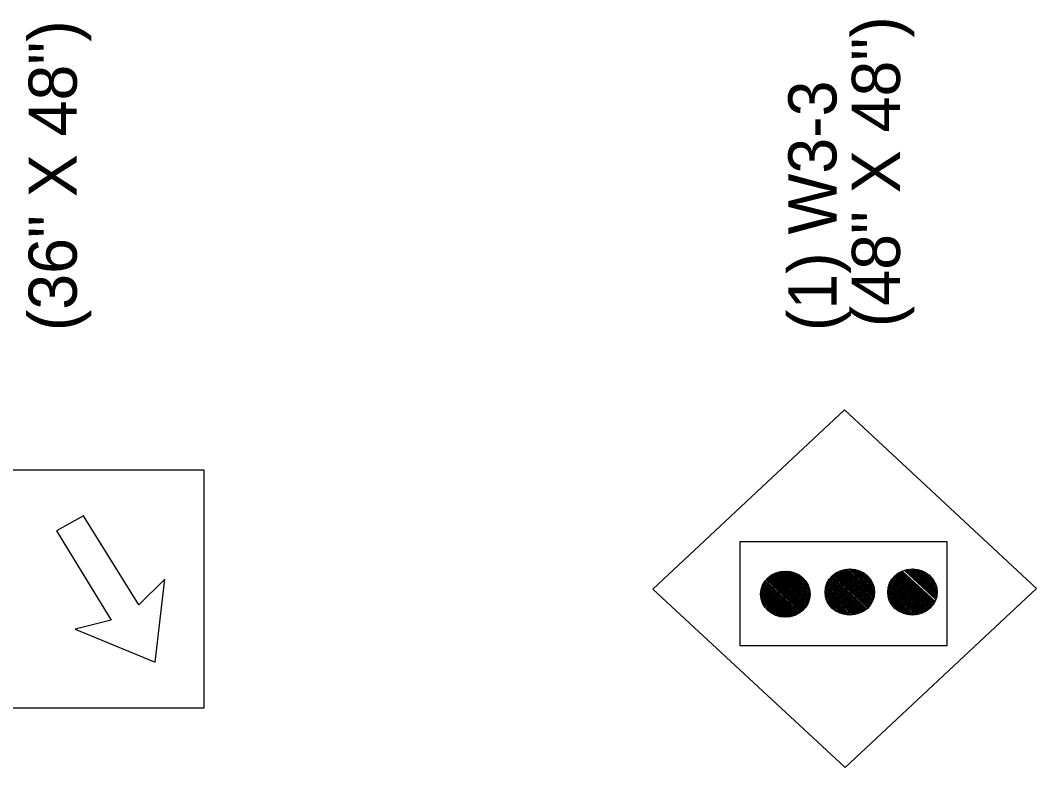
# Model space of a CAD drawing. Extents: x 1807779 to 1818251, y 673292 to 678849.
# Drawn here: x 1811509.5 to 1811641.6, y 676750 to 676847.2 of the extents above; entities that cross this region are included whole.
import ezdxf

# ---------------------------------------------------------------- set-up
doc = ezdxf.new("R2010")
doc.units = 0
doc.layers.add('Default', color=7, linetype='Continuous')

msp = doc.modelspace()

# ---------------------------------------------------------------- linework, layer by layer
at = {"layer": 'Default'}
for p, q in [((1811616.61, 676796.54), (1811591.73, 676773.26)), ((1811616.61, 676796.54), (1811641.6, 676773.34)), ((1811612, 676771.68), (1811607.95, 676775.45)), ((1811612.05, 676771.82), (1811608.11, 676775.5)), ((1811612.09, 676771.97), (1811608.27, 676775.53)), ((1811612.12, 676772.13), (1811608.43, 676775.56)), ((1811612.14, 676772.29), (1811608.61, 676775.58)), ((1811612.16, 676772.46), (1811608.79, 676775.6)), ((1811612.16, 676772.64), (1811608.99, 676775.6)), ((1811612.15, 676772.84), (1811609.2, 676775.59)), ((1811612.12, 676773.05), (1811609.42, 676775.57)), ((1811612.08, 676773.27), (1811609.66, 676775.52)), ((1811612, 676773.53), (1811609.94, 676775.45)), ((1811620.08, 676771.32), (1811615.66, 676775.44)), ((1811620.15, 676771.44), (1811615.78, 676775.51)), ((1811620.22, 676771.56), (1811615.91, 676775.57)), ((1811620.28, 676771.69), (1811616.05, 676775.63)), ((1811620.34, 676771.82), (1811616.19, 676775.68)), ((1811620.39, 676771.96), (1811616.34, 676775.73)), ((1811620.43, 676772.1), (1811616.49, 676775.77)), ((1811620.47, 676772.25), (1811616.65, 676775.81)), ((1811620.5, 676772.4), (1811616.82, 676775.84)), ((1811620.52, 676772.56), (1811616.99, 676775.86)), ((1811620.54, 676772.74), (1811617.18, 676775.87)), ((1811620.54, 676772.92), (1811617.37, 676775.87)), ((1811620.53, 676773.11), (1811617.58, 676775.86)), ((1811620.51, 676773.32), (1811617.8, 676775.84)), ((1811620.46, 676773.55), (1811618.05, 676775.8)), ((1811620.38, 676773.8), (1811618.32, 676775.73)), ((1811620.26, 676774.1), (1811618.64, 676775.61)), ((1811628.25, 676771.37), (1811623.85, 676775.47)), ((1811628.32, 676771.49), (1811623.98, 676775.54)), ((1811628.39, 676771.62), (1811624.11, 676775.6)), ((1811628.5, 676771.88), (1811624.4, 676775.7)), ((1811628.55, 676772.02), (1811624.55, 676775.75)), ((1811628.59, 676772.16), (1811624.7, 676775.79)), ((1811628.63, 676772.31), (1811624.86, 676775.82)), ((1811628.65, 676772.47), (1811625.03, 676775.85)), ((1811628.67, 676772.64), (1811625.21, 676775.86)), ((1811628.68, 676772.82), (1811625.4, 676775.87)), ((1811628.68, 676773), (1811625.6, 676775.87)), ((1811628.66, 676773.2), (1811625.82, 676775.86)), ((1811628.63, 676773.42), (1811626.05, 676775.82)), ((1811628.57, 676773.66), (1811626.31, 676775.77)), ((1811628.48, 676773.93), (1811626.6, 676775.68)), ((1811628.32, 676774.26), (1811626.96, 676775.53)), ((1811610.61, 676770.03), (1811606.18, 676774.15)), ((1811610.73, 676770.1), (1811606.26, 676774.26)), ((1811610.84, 676770.18), (1811606.34, 676774.37)), ((1811610.96, 676770.26), (1811606.43, 676774.48)), ((1811611.06, 676770.34), (1811606.52, 676774.58)), ((1811611.17, 676770.43), (1811606.61, 676774.67)), ((1811611.27, 676770.52), (1811606.71, 676774.77)), ((1811611.36, 676770.62), (1811606.82, 676774.85)), ((1811611.45, 676770.72), (1811606.92, 676774.94)), ((1811611.54, 676770.83), (1811607.04, 676775.02)), ((1811611.62, 676770.93), (1811607.15, 676775.09)), ((1811611.69, 676771.05), (1811607.27, 676775.17)), ((1811611.77, 676771.16), (1811607.4, 676775.23)), ((1811611.83, 676771.29), (1811607.53, 676775.3)), ((1811611.9, 676771.41), (1811607.67, 676775.35)), ((1811611.95, 676771.54), (1811607.81, 676775.41)), ((1811611.88, 676773.83), (1811610.26, 676775.33)), ((1811611.64, 676774.24), (1811610.7, 676775.11)), ((1811618.73, 676770.18), (1811614.43, 676774.19)), ((1811618.86, 676770.24), (1811614.49, 676774.31)), ((1811618.99, 676770.31), (1811614.57, 676774.43)), ((1811619.11, 676770.38), (1811614.64, 676774.54)), ((1811619.23, 676770.45), (1811614.73, 676774.65)), ((1811619.34, 676770.53), (1811614.81, 676774.75)), ((1811619.45, 676770.62), (1811614.9, 676774.85)), ((1811619.55, 676770.71), (1811615, 676774.95)), ((1811619.65, 676770.8), (1811615.1, 676775.04)), ((1811619.74, 676770.9), (1811615.2, 676775.13)), ((1811619.83, 676771), (1811615.31, 676775.21)), ((1811619.92, 676771.1), (1811615.42, 676775.29)), ((1811620, 676771.21), (1811615.54, 676775.37)), ((1811620.02, 676774.51), (1811619.08, 676775.39)), ((1811626.8, 676770.14), (1811622.53, 676774.12)), ((1811626.93, 676770.2), (1811622.6, 676774.24)), ((1811627.06, 676770.27), (1811622.67, 676774.36)), ((1811627.18, 676770.34), (1811622.74, 676774.48)), ((1811627.3, 676770.41), (1811622.82, 676774.59)), ((1811627.42, 676770.49), (1811622.91, 676774.69)), ((1811627.53, 676770.57), (1811622.99, 676774.8)), ((1811627.63, 676770.66), (1811623.09, 676774.9)), ((1811627.74, 676770.75), (1811623.18, 676774.99)), ((1811627.83, 676770.84), (1811623.28, 676775.08)), ((1811627.93, 676770.94), (1811623.39, 676775.17)), ((1811628.01, 676771.04), (1811623.5, 676775.25)), ((1811628.1, 676771.15), (1811623.61, 676775.33)), ((1811628.18, 676771.26), (1811623.73, 676775.4)), ((1811627.89, 676774.85), (1811627.58, 676775.13)), ((1811591.73, 676773.26), (1811616.7, 676750.05)), ((1811609.27, 676769.61), (1811605.74, 676772.91)), ((1811609.45, 676769.64), (1811605.76, 676773.07)), ((1811609.61, 676769.67), (1811605.79, 676773.23)), ((1811609.77, 676769.7), (1811605.83, 676773.38)), ((1811609.93, 676769.74), (1811605.87, 676773.52)), ((1811610.07, 676769.79), (1811605.93, 676773.65)), ((1811610.21, 676769.84), (1811605.98, 676773.79)), ((1811610.35, 676769.9), (1811606.04, 676773.91)), ((1811610.48, 676769.96), (1811606.11, 676774.03)), ((1811617.28, 676769.87), (1811614.1, 676772.83)), ((1811617.47, 676769.88), (1811614.11, 676773.01)), ((1811617.65, 676769.89), (1811614.12, 676773.18)), ((1811617.83, 676769.91), (1811614.14, 676773.35)), ((1811618, 676769.94), (1811614.17, 676773.5)), ((1811618.16, 676769.98), (1811614.21, 676773.65)), ((1811618.31, 676770.02), (1811614.26, 676773.79)), ((1811618.46, 676770.07), (1811614.31, 676773.93)), ((1811618.6, 676770.12), (1811614.37, 676774.06)), ((1811641.6, 676773.34), (1811616.7, 676750.05)), ((1811625.51, 676769.87), (1811622.24, 676772.91)), ((1811625.7, 676769.88), (1811622.25, 676773.09)), ((1811625.88, 676769.9), (1811622.27, 676773.26)), ((1811626.05, 676769.92), (1811622.3, 676773.42)), ((1811626.21, 676769.95), (1811622.33, 676773.57)), ((1811626.37, 676769.99), (1811622.37, 676773.71)), ((1811626.52, 676770.04), (1811622.42, 676773.85)), ((1811626.66, 676770.09), (1811622.48, 676773.99)), ((1811609.09, 676769.6), (1811605.72, 676772.74)), ((1811608.89, 676769.6), (1811605.72, 676772.56)), ((1811608.68, 676769.61), (1811605.73, 676772.36)), ((1811608.46, 676769.63), (1811605.75, 676772.15)), ((1811608.22, 676769.67), (1811605.8, 676771.93)), ((1811607.94, 676769.75), (1811605.88, 676771.67)), ((1811617.07, 676769.88), (1811614.11, 676772.64)), ((1811616.84, 676769.91), (1811614.14, 676772.43)), ((1811616.6, 676769.95), (1811614.18, 676772.2)), ((1811616.33, 676770.02), (1811614.26, 676771.95)), ((1811616, 676770.14), (1811614.38, 676771.64)), ((1811625.3, 676769.88), (1811622.25, 676772.72)), ((1811625.09, 676769.89), (1811622.27, 676772.52)), ((1811624.85, 676769.93), (1811622.3, 676772.3)), ((1811624.59, 676769.98), (1811622.36, 676772.06)), ((1811624.3, 676770.08), (1811622.46, 676771.79)), ((1811607.62, 676769.86), (1811606, 676771.37)), ((1811607.19, 676770.08), (1811606.24, 676770.96)), ((1811615.57, 676770.36), (1811614.62, 676771.24)), ((1811623.93, 676770.24), (1811622.63, 676771.44))]:
    msp.add_line(p, q, dxfattribs=at)
for points in [[(1811483.49, 676788.75), (1811533.38, 676788.75), (1811533.38, 676757.76), (1811483.49, 676757.76)], [(1811514.21, 676780.83), (1811521.33, 676769.22), (1811516.67, 676768.06), (1811527.03, 676763.75), (1811528.28, 676774.55), (1811524.91, 676771.19), (1811517.75, 676782.76)], [(1811603.08, 676765.89), (1811603.08, 676779.45), (1811629.93, 676779.45), (1811629.93, 676765.89)]]:
    msp.add_lwpolyline(points, close=True, dxfattribs=at)
for centre in [(1811608.94, 676772.6), (1811617.32, 676772.87), (1811625.46, 676772.87)]:
    msp.add_ellipse(centre, major_axis=(3.22, 0), ratio=0.93178, dxfattribs=at)

# ---------------------------------------------------------------- texts
for s, height, p in [('(48" X 48")', 6.2623, (1811623.84, 676807.29)), ('(36" X 48")', 6.2623, (1811516.86, 676806.77)), ('(1) W3-3', 6.262, (1811615.59, 676806.77))]:
    msp.add_text(s, height=height, rotation=90, dxfattribs=at).set_placement(p)

doc.saveas('drawing.dxf')
